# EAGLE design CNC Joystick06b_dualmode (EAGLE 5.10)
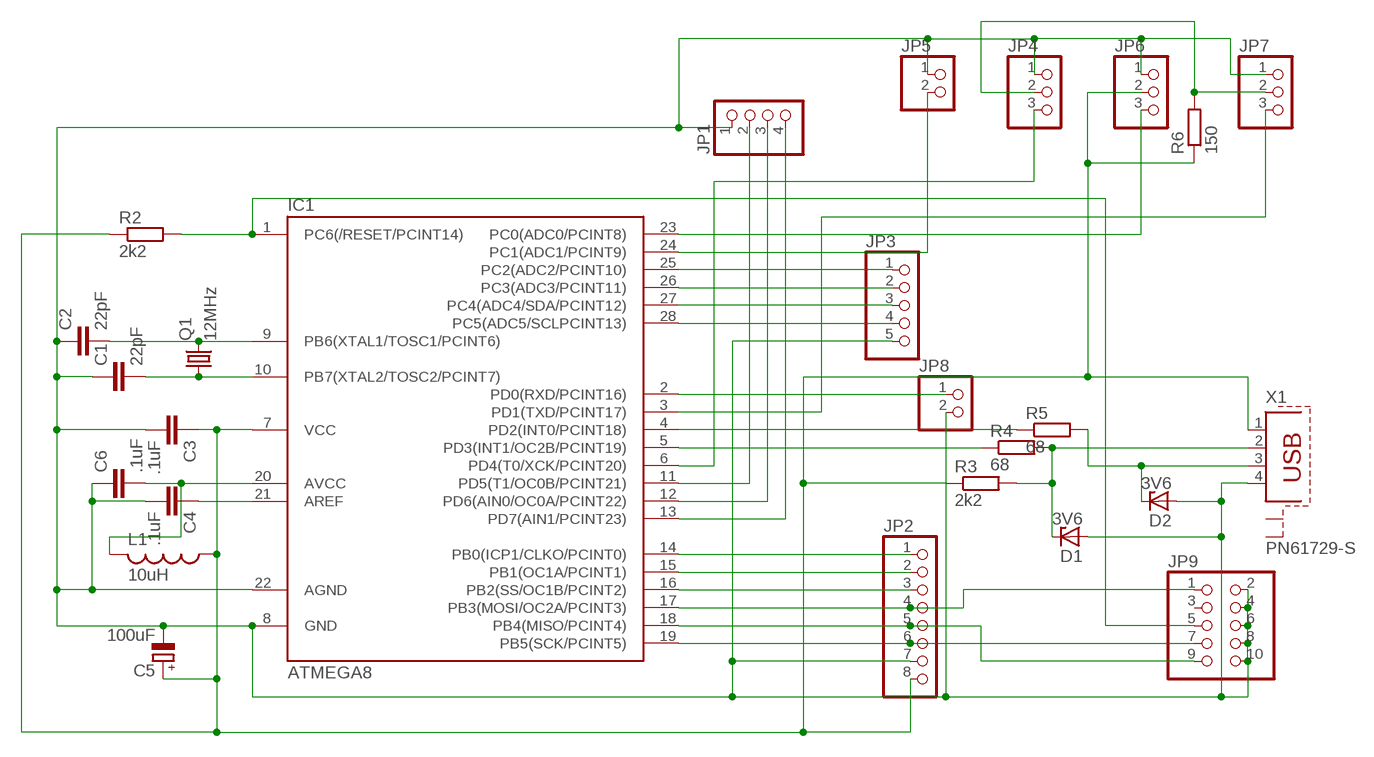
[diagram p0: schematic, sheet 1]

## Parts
C1  22pF  C-EU025-025X050  [C025-025X050]
C2  22pF  C-EU025-025X050  [C025-025X050]
C3  .1uF  C-EU025-025X050  [C025-025X050]
C4  .1uF  C-EU025-025X050  [C025-025X050]
C5  100uF  CPOL-EUE2,5-6E  [E2,5-6E]
C6  .1uF  C-EU050-024X044  [C050-024X044]
D1  3V6  ZENER-DIODEZD-5  [ZDIO-5]
D2  3V6  ZENER-DIODEZD-7.5  [ZDIO-7.5]
IC1  ATMEGA8  ATMEGA48/88/168-PU  [DIL28-3]
JP1  PINHD-1X4  [1X04]
JP2  PINHD-1X8  [1X08]
JP3  PINHD-1X5  [1X05]
JP4  PINHD-1X3  [1X03]
JP5  PINHD-1X2  [1X02]
JP6  PINHD-1X3  [1X03]
JP7  PINHD-1X3  [1X03]
JP8  PINHD-1X2  [1X02]
JP9  PINHD-2X5/90  [2X05/90]
L1  10uH  L-US0204/5  [0204/5]
Q1  12MHz  CRYSTALHC49S  [HC49/S]
R2  2k2  R-EU_0204/7  [0204/7]
R3  2k2  R-EU_0204/7  [0204/7]
R4  68  R-EU_0204/7  [0204/7]
R5  68  R-EU_0204/7  [0204/7]
R6  150  R-EU_0207/10  [0207/10]
X1  PN61729-S  [PN61729-S]

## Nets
N$1: C3.1 C5.+ IC1.7(VCC) JP2.8 JP6.2 L1.1 R2.1 R3.1 R6.1 X1.1
N$2: IC1.17(PB3(MOSI/OC2A/PCINT3)) JP2.4 JP9.1
N$3: IC1.18(PB4(MISO/PCINT4)) JP2.5 JP9.9
N$4: IC1.19(PB5(SCK/PCINT5)) JP2.6 JP9.7
N$5: IC1.11(PD5(T1/OC0B/PCINT21)) JP1.2
N$6: IC1.12(PD6(AIN0/OC0A/PCINT22)) JP1.3
N$7: IC1.13(PD7(AIN1/PCINT23)) JP1.4
N$8: IC1.15(PB1(OC1A/PCINT1)) JP2.2
N$9: IC1.14(PB0(ICP1/CLKO/PCINT0)) JP2.1
N$10: IC1.16(PB2(SS/OC1B/PCINT2)) JP2.3
N$11: IC1.28(PC5(ADC5/SCLPCINT13)) JP3.4
N$12: IC1.27(PC4(ADC4/SDA/PCINT12)) JP3.3
N$13: IC1.26(PC3(ADC3/PCINT11)) JP3.2
N$14: IC1.25(PC2(ADC2/PCINT10)) JP3.1
N$15: IC1.3(PD1(TXD/PCINT17)) JP7.3
N$16: IC1.2(PD0(RXD/PCINT16)) JP8.1
N$18: IC1.23(PC0(ADC0/PCINT8)) JP6.3
N$19: IC1.24(PC1(ADC1/PCINT9)) JP5.2
N$20: IC1.6(PD4(T0/XCK/PCINT20)) JP4.3
N$22: JP4.2 JP7.2 R6.2
N$23: C1.1 C2.1 C3.2 C4.2 C5.- C6.1 D1.A D2.A IC1.8(GND) IC1.22(AGND) JP1.1 JP2.7 JP3.5 JP4.1 JP5.1 JP6.1 JP7.1 JP8.2 JP9.2 JP9.4 JP9.6 JP9.8 JP9.10 X1.4
N$31: D2.C R5.2 X1.3
N$32: IC1.5(PD3(INT1/OC2B/PCINT19)) R4.1
N$35: C2.2 IC1.9(PB6(XTAL1/TOSC1/PCINT6)) Q1.2
N$36: C1.2 IC1.10(PB7(XTAL2/TOSC2/PCINT7)) Q1.1
N$37: IC1.4(PD2(INT0/PCINT18)) R5.1
N$43: IC1.1(PC6(/RESET/PCINT14)) JP9.5 R2.2
N$48: D1.C R3.2 R4.2 X1.2
N$62: C6.2 IC1.20(AVCC) L1.2
N$63: C4.1 IC1.21(AREF)
Unconnected: JP9.3 X1.S1 X1.S2

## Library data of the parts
C1-C4 C6 = rcl:C-EU: CAPACITOR, European symbol
C5 = rcl:CPOL-EU: POLARIZED CAPACITOR, European symbol
D1 D2 = diode:ZENER-DIODE: Z-Diode
IC1 = atmega8:ATMEGA48/88/168-PU
JP1 = pinhead:PINHD-1X4: PIN HEADER
JP2 = pinhead:PINHD-1X8: PIN HEADER
JP3 = pinhead:PINHD-1X5: PIN HEADER
JP4 JP6 JP7 = pinhead:PINHD-1X3: PIN HEADER
JP5 JP8 = pinhead:PINHD-1X2: PIN HEADER
JP9 = pinhead:PINHD-2X5: PIN HEADER
L1 = rcl:L-US: INDUCTOR, American symbol
Q1 = crystal:CRYSTAL: CRYSTAL
R2-R6 = rcl:R-EU_: RESISTOR, European symbol
X1 = con-berg:PN61729-S: BERG USB connector

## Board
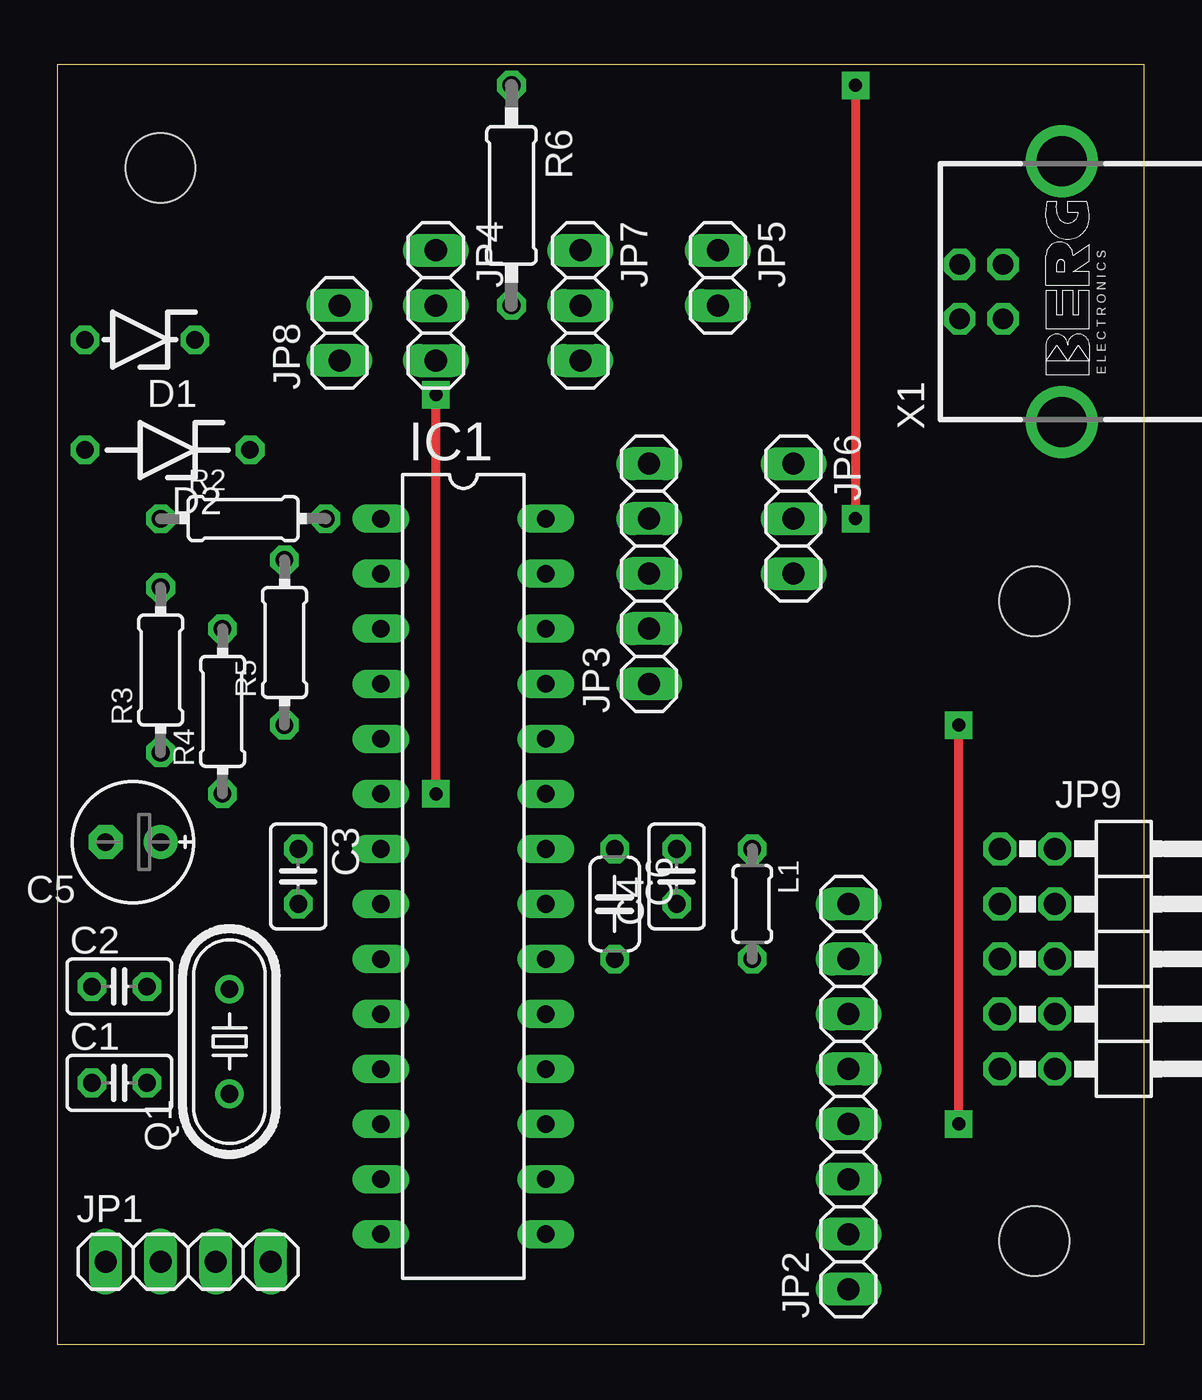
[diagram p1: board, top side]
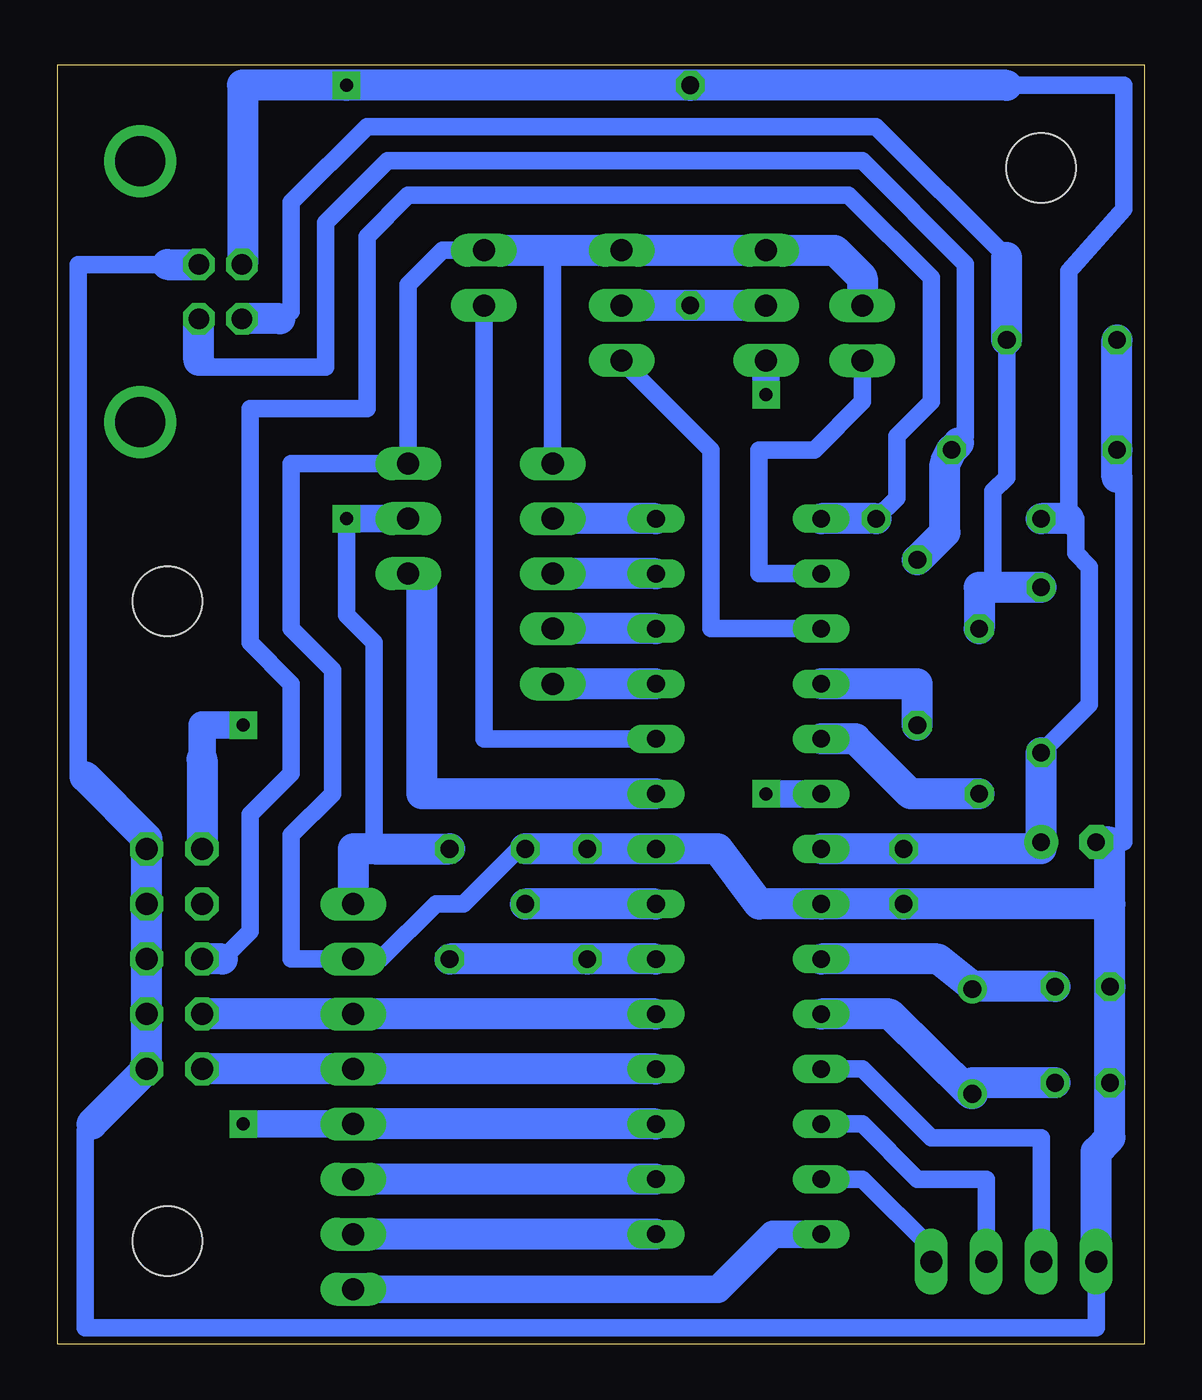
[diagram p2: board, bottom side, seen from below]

Size 50.15 x 59.05 mm. Coordinates in mm from the lower left corner, seen from the top.
Outline: 0,0 50.15,0 50.15,59.05 0,59.05 0,0
Copper layers (1*16): Top 0.035mm / dielectric 1.5mm / Bottom 0.035mm
Design rules "default": minimum track width 10mil, minimum drill 24mil, track to track 8mil, track to pad 8mil, pad to pad 8mil, via to via 8mil, smd to smd 8mil, copper to edge 40mil, drill to drill 8mil, minimum pad ring 10mil, minimum via ring 8mil, stop-mask expansion 4mil, vias tented up to drill 0mil, thermal gap 10mil
Holes 3.2 mm at 45.09,4.76 4.76,54.29 45.09,34.29
tRestrict: area 41.1,0.8 to 49.1,8.7; area 0.8,50.3 to 8.7,58.3; area 41.1,30.3 to 49.1,38.3

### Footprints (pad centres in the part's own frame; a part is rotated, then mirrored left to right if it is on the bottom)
C025-025X050 = drill 0.813 octagon: 1 -1.27,0; 2 1.27,0
E2,5-6E = drill 0.813 pad 1.575 round: + -1.27,0 | drill 0.813 pad 1.575 octagon: - 1.27,0
C050-024X044 = drill 0.813 octagon: 1 -2.54,0; 2 2.54,0
ZDIO-5 = drill 0.813 octagon: A 2.54,0; C -2.54,0
ZDIO-7.5 = drill 0.813 octagon: A 3.81,0; C -3.81,0
DIL28-3 = drill 0.813 long: 1 -16.51,-3.81; 2 -13.97,-3.81; 3 -11.43,-3.81; 4 -8.89,-3.81; 5 -6.35,-3.81; 6 -3.81,-3.81; 7 -1.27,-3.81; 8 1.27,-3.81; 9 3.81,-3.81; 10 6.35,-3.81; 11 8.89,-3.81; 12 11.43,-3.81; 13 13.97,-3.81; 14 16.51,-3.81; 15 16.51,3.81; 16 13.97,3.81; 17 11.43,3.81; 18 8.89,3.81; 19 6.35,3.81; 20 3.81,3.81; 21 1.27,3.81; 22 -1.27,3.81; 23 -3.81,3.81; 24 -6.35,3.81; 25 -8.89,3.81; 26 -11.43,3.81; 27 -13.97,3.81; 28 -16.51,3.81
1X04 = drill 1.016 long: 1 -3.81,0; 2 -1.27,0; 3 1.27,0; 4 3.81,0
1X08 = drill 1.016 long: 1 -8.89,0; 2 -6.35,0; 3 -3.81,0; 4 -1.27,0; 5 1.27,0; 6 3.81,0; 7 6.35,0; 8 8.89,0
1X05 = drill 1.016 long: 1 -5.08,0; 2 -2.54,0; 3 0,0; 4 2.54,0; 5 5.08,0
1X03 = drill 1.016 long: 1 -2.54,0; 2 0,0; 3 2.54,0
1X02 = drill 1.016 long: 1 -1.27,0; 2 1.27,0
2X05/90 = drill 1.016 octagon: 1 -5.08,-6.35; 2 -5.08,-3.81; 3 -2.54,-6.35; 4 -2.54,-3.81; 5 0,-6.35; 6 0,-3.81; 7 2.54,-6.35; 8 2.54,-3.81; 9 5.08,-6.35; 10 5.08,-3.81
0204/5 = drill 0.813 octagon: 1 -2.54,0; 2 2.54,0
HC49/S = drill 0.813 round: 1 -2.413,0; 2 2.413,0
0204/7 = drill 0.813 octagon: 1 -3.81,0; 2 3.81,0
0207/10 = drill 0.813 octagon: 1 -5.08,0; 2 5.08,0
PN61729-S = drill 0.95 octagon: 1 1.25,4.71; 2 -1.25,4.71; 3 -1.25,2.71; 4 1.25,2.71 | drill 2.3 pad 2.9 round: S1 -6.02,0; S2 6.02,0

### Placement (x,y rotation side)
C1  2.86,12.06 0 top
C2  2.86,16.51 0 top
C3  11.11,21.59 270 top
C4  28.57,21.59 90 top
C5  3.49,23.18 180 top
C6  25.72,20.32 270 top
D1  3.81,46.35 180 top
D2  5.08,41.27 180 top
IC1  18.73,21.59 270 top
JP1  6.03,3.81 0 top
JP2  36.51,11.43 90 top
JP3  27.3,35.56 90 top
JP4  17.46,47.94 270 top
JP5  30.48,49.21 270 top
JP6  33.97,38.1 270 top
JP7  24.13,47.94 270 top
JP8  13.02,46.67 90 top
JP9  49.85,17.78 270 top
L1  32.07,20.32 270 top
Q1  7.94,13.97 90 top
R2  8.57,38.1 0 top
R3  4.76,31.11 90 top
R4  7.62,29.21 90 top
R5  10.48,32.38 90 top
R6  20.95,53.02 270 top
X1  46.35,48.58 90 top

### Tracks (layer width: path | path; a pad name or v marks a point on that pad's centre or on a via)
N$1  (via drill 0.6 pad 1.27)
  Top 0.406: v36.83,58.1 v36.83,38.1
  Bottom 0.813: R3.1 2.54,29.53 2.54,35.88 3.17,36.51 3.17,38.1 3.49,38.1 3.49,49.53 0.95,52.39 0.95,58.1 6.35,58.1 | v36.83,38.1 36.83,33.66 35.56,32.38 35.56,22.86
  Bottom 1.27: v36.83,38.1 JP6.2
  Bottom 1.422: 3.49,38.1 R2.1 | R3.1 C5.+ 4.76,22.86 C3.1 IC1.7 | X1.1 41.63,49.86 41.63,58.12 v36.83,58.1 R6.1 6.35,58.1 | JP2.8 36.51,22.86 35.56,22.86 L1.1
N$2  (via drill 0.6 pad 1.27)
  Top 0.406: v41.59,10.16 v41.59,28.57
  Bottom 1.27: v41.59,28.57 43.5,28.57 43.5,26.99 | JP2.4 v41.59,10.16
  Bottom 1.422: IC1.17 JP2.4 | 43.5,26.99 JP9.1
N$3
  Bottom 1.422: IC1.18 JP2.5 JP9.9
N$4
  Bottom 1.422: IC1.19 JP2.6 JP9.7
N$5
  Bottom 0.813: JP1.2 4.76,9.53 9.84,9.53 13.02,12.7 IC1.11
N$6
  Bottom 0.813: JP1.3 7.3,7.62 10.48,7.62 13.02,10.16 IC1.12
N$7
  Bottom 0.813: IC1.13 13.02,7.62 9.84,4.45 JP1.4
N$8
  Bottom 1.422: IC1.15 JP2.2
N$9
  Bottom 1.27: JP2.1 19.68,2.54 17.14,5.08 IC1.14
N$10
  Bottom 1.422: IC1.16 JP2.3
N$11
  Bottom 1.422: IC1.28 JP3.4
N$12
  Bottom 1.422: IC1.27 JP3.3
N$13
  Bottom 1.422: IC1.26 JP3.2
N$14
  Bottom 1.422: IC1.25 JP3.1
N$15
  Bottom 0.813: IC1.3 20,33.02 20,41.27 JP7.3
N$16
  Bottom 0.813: IC1.2 17.78,35.56 17.78,41.27 15.24,41.27 13.02,43.5 JP8.1
N$18
  Bottom 1.422: IC1.23 33.34,25.4 33.34,35.56 JP6.3
N$19
  Bottom 0.813: IC1.24 30.48,27.94 JP5.2
N$20  (via drill 0.6 pad 1.27)
  Top 0.406: v17.46,25.4 v17.46,43.81
  Bottom 1.27: IC1.6 v17.46,25.4 | v17.46,43.81 JP4.3
N$22
  Bottom 1.422: JP7.2 R6.2 JP4.2
N$23
  Bottom 0.813: C4.2 28.89,22.86 31.43,20.32 32.7,20.32 35.24,17.78 JP2.7 39.37,17.78 39.37,23.5 37.47,25.4 37.47,31.11 39.37,33.02 39.37,40.64 JP6.1 33.97,48.9 32.38,50.48 JP5.1 | 27.3,50.48 JP3.5 | 45.09,49.83 49.21,49.83 49.21,26.35 48.9,26.19 | JP1.1 2.22,0.76 48.9,0.76 48.9,9.84 48.58,10.16 | C5.- 0.95,23.18 0.95,40.01 1.27,40.01
  Bottom 1.422: C4.2 C6.1 IC1.22 19.68,22.86 17.78,20.32 IC1.8 C3.2 1.59,20.32 | JP1.1 2.22,8.89 1.59,9.53 C1.1 C2.1 1.59,20.32 | JP8.2 13.02,49.21 14.29,50.48 JP4.1 JP7.1 27.3,50.48 JP5.1 | 45.09,49.83 X1.4 | D1.A D2.A 1.27,40.01 | C5.- 1.59,23.18 1.59,20.32 | 48.58,10.16 JP9.10 JP9.8 JP9.6 JP9.4 JP9.2 46.04,23.34 48.9,26.19
N$31
  Bottom 0.813: 8.57,41.59 8.26,41.91 8.26,49.85 13.02,54.61 34.92,54.61 37.78,51.75 37.78,45.09 43.5,45.09 43.64,45.41
  Bottom 1.422: 43.64,45.41 X1.3 | R5.2 9.21,37.47 9.21,40.64 D2.C 8.57,41.59
N$32
  Bottom 1.422: R4.1 10.79,25.4 13.34,27.94 IC1.5
N$35
  Bottom 0.406: 7.94,16.51 Q1.2
  Bottom 1.422: IC1.9 9.53,17.78 7.94,16.51 C2.2
N$36
  Bottom 0.813: Q1.1 8,11.56
  Bottom 1.422: 8,11.56 11.75,15.24 IC1.10 | C1.2 7.94,12.06 Q1.1
N$37
  Bottom 1.422: R5.1 10.48,30.48 IC1.4
N$43
  Bottom 0.813: R2.2 11.43,39.05 11.43,41.91 9.84,43.5 9.84,49.21 13.65,53.02 33.97,53.02 35.88,51.12 35.88,43.18 41.27,43.18 41.27,32.38 39.37,30.48 39.37,26.35 41.27,24.45 41.27,19.05 42.55,17.78
  Bottom 1.422: R2.2 IC1.1 | 42.55,17.78 JP9.5
N$48
  Bottom 0.813: 6.35,50.16 12.38,56.2 35.88,56.2 39.37,52.7 39.37,47.66 39.89,47.33 | D1.C 6.35,40.01 6.99,39.37 6.99,34.92
  Bottom 1.422: D1.C 6.35,50.16 | R4.2 7.62,34.92 6.99,34.92 R3.2 | 39.89,47.33 X1.2
N$62
  Bottom 1.422: IC1.20 C6.2 L1.2
N$63
  Bottom 1.422: IC1.21 C4.1

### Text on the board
Document: Zero | Regen | Stop | Spinner | Mode | GND | GND | Joystick | GND | GND | Up | 5V | Left | Down | Right | MOSI | 5V | GND | RST | D0 | SCK | D1 | MISO | GND | D2 | Clk | Rotary | Display | Din | Load | GND | R3 | R2 | R1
